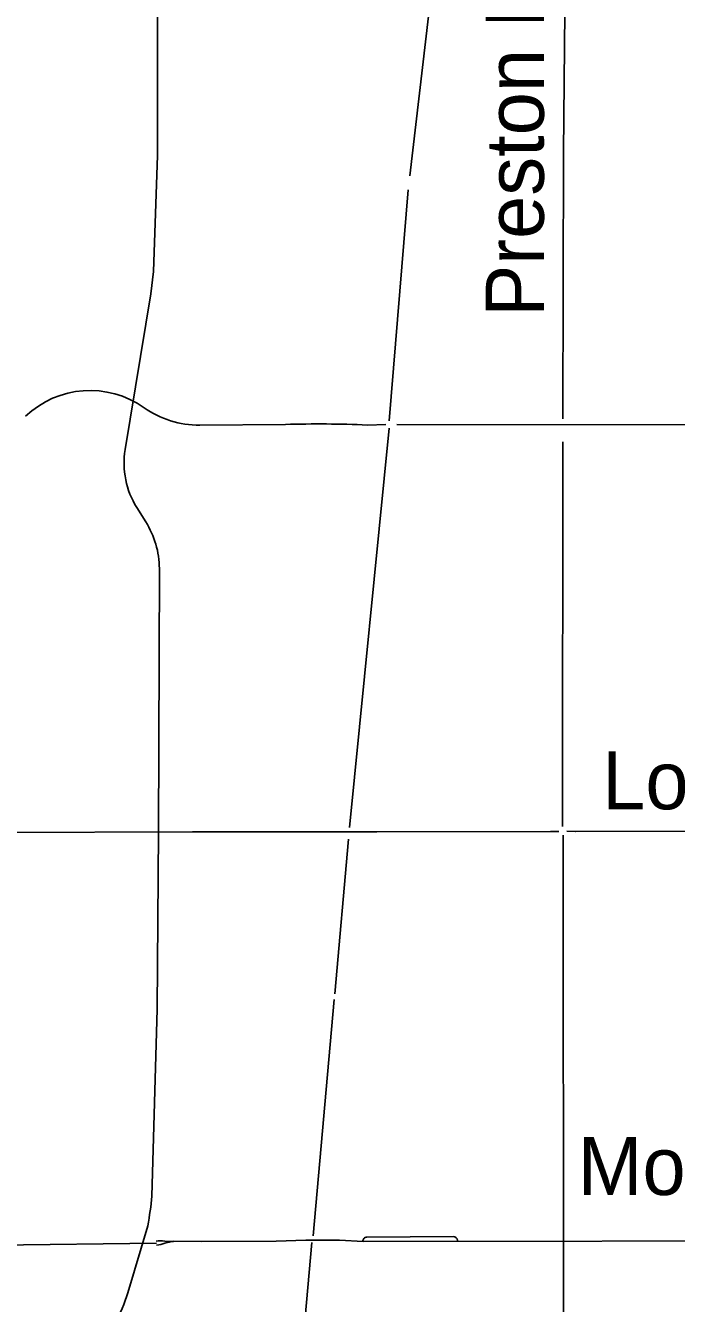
# Model space of a CAD drawing. Extents: x 105094 to 105814, y -291615 to -291123.
# Drawn here: x 105434.53 to 105448.1, y -291434.34 to -291407.68 of the extents above; entities that cross this region are included whole.
import ezdxf

# ---------------------------------------------------------------- set-up
doc = ezdxf.new("R2010")
doc.units = 0
doc.layers.add('G_MAP', color=7, linetype='Continuous')

msp = doc.modelspace()

# ---------------------------------------------------------------- linework, layer by layer
at = {"layer": 'G_MAP'}
for p, q in [((105437.282, -291410.389), (105437.282, -291403.244)), ((105442.933, -291407.489), (105442.544, -291410.814)), ((105445.736, -291415.888), (105445.746, -291410.321)), ((105442.507, -291411.109), (105442.113, -291415.924)), ((105439.949, -291416.002), (105438.16, -291416.015)), ((105442.038, -291416.005), (105441.657, -291416.014)), ((105442.113, -291416.082), (105441.282, -291424.411)), ((105445.729, -291424.391), (105445.736, -291416.363)), ((105436.848, -291417.737), (105437.036, -291418.035)), ((105428.029, -291424.534), (105438.011, -291424.501)), ((105441.857, -291424.498), (105438.011, -291424.501)), ((105445.484, -291424.491), (105441.857, -291424.498)), ((105445.652, -291424.491), (105445.477, -291424.491)), ((105445.994, -291424.491), (105445.817, -291424.488)), ((105441.263, -291424.65), (105440.975, -291427.879)), ((105445.749, -291435.439), (105445.739, -291424.569)), ((105440.966, -291427.996), (105440.523, -291432.927)), ((105437.077, -291432.714), (105436.66, -291434.112)), ((105437.255, -291433.076), (105432.259, -291433.141)), ((105440.501, -291433.066), (105440.281, -291435.462)), ((105440.375, -291433.014), (105440.652, -291433.014)), ((105440.649, -291433.014), (105441.075, -291433.014)), ((105441.645, -291432.953), (105443.451, -291432.943))]:
    msp.add_line(p, q, dxfattribs=at)
for points in [[(105445.746, -291410.321), (105445.797, -291405.189), (105445.784, -291399.648), (105445.775, -291398.734), (105445.73, -291396.218)], [(105437.282, -291410.389), (105437.198, -291412.808), (105437.139, -291413.279), (105436.604, -291416.527)], [(105462.448, -291415.962), (105454.301, -291416.011), (105442.268, -291416.005)], [(105437.317, -291419.008), (105437.297, -291424.508), (105437.274, -291428.196), (105437.161, -291432.097)], [(105460.814, -291424.397), (105456.296, -291424.413), (105454.3, -291424.436), (105452.77, -291424.404), (105450.331, -291424.488), (105445.991, -291424.491)], [(105437.61, -291433.04), (105438.192, -291433.047), (105439.755, -291433.034), (105440.375, -291433.014)], [(105441.075, -291433.014), (105441.566, -291433.046), (105451.529, -291433.03), (105452.947, -291432.988), (105457.811, -291432.971)]]:
    msp.add_lwpolyline(points, dxfattribs=at)
for centre, radius, start, end in [((105435.872, -291417.246), 1.952, 54.7012, 133.5509), ((105438.145, -291414.026), 1.989, 234.8608, 270.433), ((105440.634, -291438.519), 22.528, 87.3964, 91.7425), ((105438.323, -291416.81), 1.742, 170.6607, 212.1249), ((105435.477, -291419.014), 1.84, 0.1947, 32.1327), ((105430.862, -291431.554), 6.322, 349.4247, 355.0687), ((105437.326, -291433.788), 0.758, 82.0949, 95.7131), ((105437.184, -291432.364), 0.758, 275.7132, 289.3314), ((105437.535, -291432.286), 0.758, 262.095, 275.7132), ((105437.686, -291433.795), 0.758, 95.7131, 109.3313), ((105441.646, -291433.036), 0.0829, 90.2902, 184.9377), ((105443.45, -291433.029), 0.0862, 3.5012, 89.8175), ((105434.279, -291433.449), 2.471, 312.2494, 344.4413)]:
    msp.add_arc(centre, radius, start, end, dxfattribs=at)

# ---------------------------------------------------------------- texts
msp.add_text('Preston Rd.', height=1.21107, rotation=90, dxfattribs=at).set_placement((105445.337, -291413.751))
for s, height, p in [('Lovers Ln.', 1.2111, (105446.554, -291424.029)), ('Mockingbird Ln.', 1.21107, (105446.045, -291432.074))]:
    msp.add_text(s, height=height, dxfattribs=at).set_placement(p)

doc.saveas('drawing.dxf')
